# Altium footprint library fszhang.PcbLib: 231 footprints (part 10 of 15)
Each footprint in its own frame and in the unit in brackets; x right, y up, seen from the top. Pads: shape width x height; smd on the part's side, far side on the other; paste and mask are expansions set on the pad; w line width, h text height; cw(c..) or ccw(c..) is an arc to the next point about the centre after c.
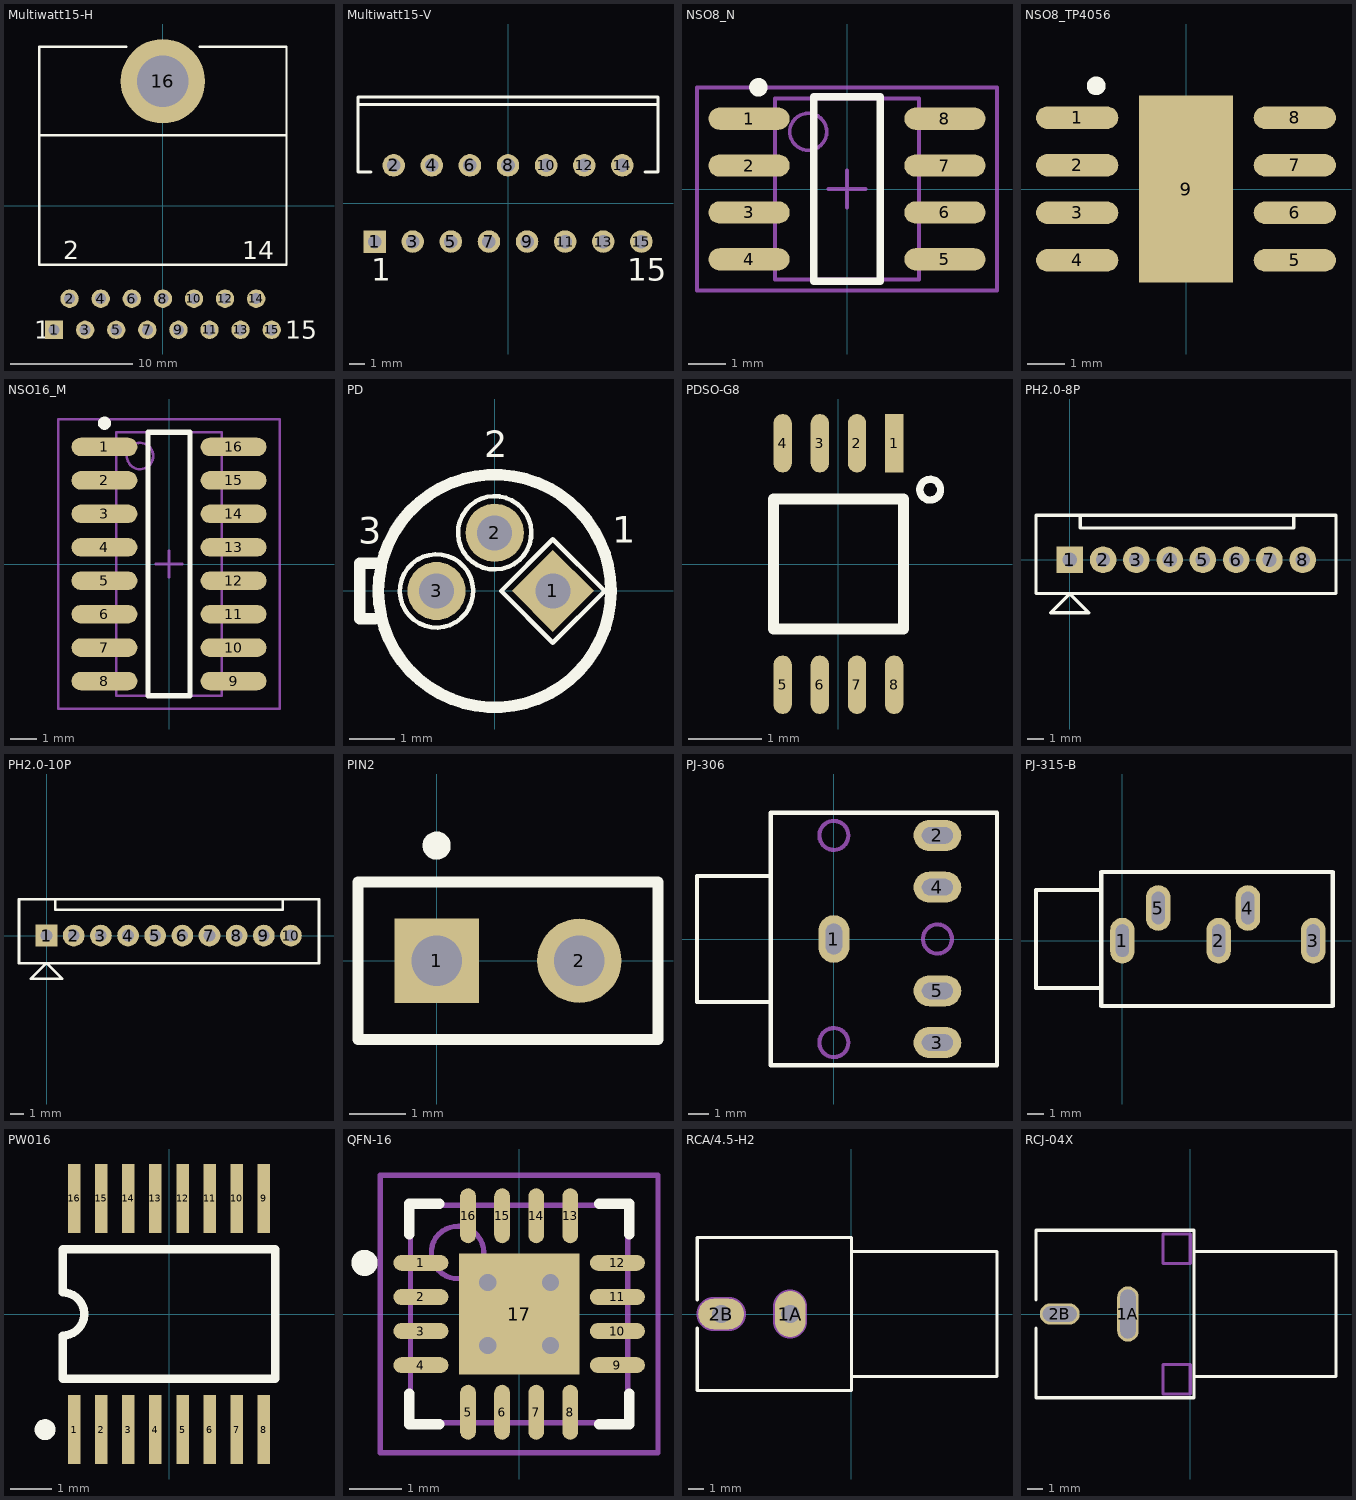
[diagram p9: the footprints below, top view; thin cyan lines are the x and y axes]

## Multiwatt15-H [mm]
height 5
pads (16):
  rect 1.5x1.5 hole 0.9: 1(-8.89,-10.155)
  round 1.5 hole 0.9: 2(-7.62,-7.615) 3(-6.35,-10.155) 4(-5.08,-7.615) 5(-3.81,-10.155) 6(-2.54,-7.615) 7(-1.27,-10.155) 8(0,-7.615) 9(1.27,-10.155) 10(2.54,-7.615) 11(3.81,-10.155) 12(5.08,-7.615) 13(6.35,-10.155) 14(7.62,-7.615) 15(8.89,-10.155)
  round 6.9 hole 4.2: 16(0,10.155)
Top Overlay:
  lines w0.2: -10.1,5.755 10.1,5.755 ; -3,12.955 -10.1,12.955 -10.1,-4.845 10.1,-4.845 10.1,12.955 3,12.955
  text "2" at -8.12,-4.37 h1.5
  text "14" at 6.495,-4.37 h1.5
  text "15" at 10.015,-10.905 h1.5
  text "1" at -10.515,-10.905 h1.5

## Multiwatt15-V [mm]
height 21
pads (15):
  rect 1.5x1.5 hole 0.9: 1(-8.89,-2.54)
  round 1.5 hole 0.9: 2(-7.62,2.54) 3(-6.35,-2.54) 4(-5.08,2.54) 5(-3.81,-2.54) 6(-2.54,2.54) 7(-1.27,-2.54) 8(0,2.54) 9(1.27,-2.54) 10(2.54,2.54) 11(3.81,-2.54) 12(5.08,2.54) 13(6.35,-2.54) 14(7.62,2.54) 15(8.89,-2.54)
Top Overlay:
  lines w0.2: -10,6.59 10,6.59 ; -9.144,2.09 -10,2.09 -10,7.09 10,7.09 10,2.09 9.144,2.09
  text "1" at -9.12,-5.165 h1.5
  text "15" at 7.94,-5.165 h1.5

## NSO8_N [mm] "SOIC-max660"
height 1.75
pads (8):
  oval 2.2x0.6 smd: 1(-2.654,1.905) 2(-2.654,0.635) 3(-2.654,-0.635) 4(-2.654,-1.905) 5(2.654,-1.905) 6(2.654,-0.635) 7(2.654,0.635) 8(2.654,1.905)
Top Overlay:
  circle w0.25: c-2.4,2.755 r0.125
  lines w0.2: -0.9,-2.5 0.9,-2.5 0.9,2.5 -0.9,2.5 -0.9,-2.5
Mechanical 13:
  circle w0.1: c-1.05,1.55 r0.5
  lines w0.1: -1.95,-2.45 1.95,-2.45 1.95,2.45 -1.95,2.45 -1.95,-2.45
Mechanical 15:
  lines w0.1: -0.5,0 0.5,0 ; 0,-0.5 0,0.5 ; -4.064,-2.75 4.064,-2.75 4.064,2.75 -4.064,2.75 -4.064,-2.75
3D body: height 1.75, standoff 0, extent -1.95,-2.45 1.95,2.45

## NSO8_TP4056 [mm] "SOIC-max660"
height 1.75
pads (9):
  oval 2.2x0.6 smd: 1(-2.908,1.905) 2(-2.908,0.635) 3(-2.908,-0.635) 4(-2.908,-1.905) 5(2.908,-1.905) 6(2.908,-0.635) 7(2.908,0.635) 8(2.908,1.905)
  rect 2.5x5 smd: 9(0,0)
Top Overlay:
  circle w0.25: c-2.4,2.755 r0.125

## NSO16_M [mm] "SOIC, 16-Leads, Body 9.9x3.9mm, Pitch 1.27mm, IPC Low Density"
height 1.75
pads (16):
  oval 2.5x0.7 smd: 1(-2.45,4.445) 2(-2.45,3.175) 3(-2.45,1.905) 4(-2.45,0.635) 5(-2.45,-0.635) 6(-2.45,-1.905) 7(-2.45,-3.175) 8(-2.45,-4.445) 9(2.45,-4.445) 10(2.45,-3.175) 11(2.45,-1.905) 12(2.45,-0.635) 13(2.45,0.635) 14(2.45,1.905) 15(2.45,3.175) 16(2.45,4.445)
Top Overlay:
  circle w0.25: c-2.45,5.345 r0.125
  lines w0.2: -0.8,-5 -0.8,5 0.8,5 0.8,-5 -0.8,-5
Mechanical 13:
  circle w0.1: c-1.1,4.1 r0.5
  lines w0.1: -2,-5 -2,5 2,5 2,-5 -2,-5
Mechanical 15:
  lines w0.1: -0.5,0 0.5,0 ; 0,-0.5 0,0.5 ; -4.2,-5.5 -4.2,5.5 4.2,5.5 4.2,-5.5 -4.2,-5.5
3D body: height 1.75, standoff 0, extent -2,-5 2,5

## PD [mil]
pads (3):
  rect 50x50 hole 30 rot 45: 1(50,0)
  round 50 hole 30: 2(0,50) 3(-50,0)
Top Overlay:
  circle w10: c0,0 r100
  lines w3.94: -18.5,1 ccw(c-50,0) -18.5,0.98 ; 5.5,0 50,-44.5 94.5,0 50,44.5 5.5,0 ; 31.5,51 ccw(c0,50) 31.5,50.98
  lines w9.84: -103,-24 -116,-24 -116,24 -102,24
  text "3" at -117.5,33 h39.37
  text "2" at -9,107 h39.37
  text "1" at 101,33.5 h39.37
Bottom Overlay:
  lines w3.94: -18.5,1 ccw(c-50,0) -18.5,0.98 ; 5.5,0 50,44.5 94.5,0 50,-44.5 5.5,0 ; 31.5,51 ccw(c0,50) 31.5,50.98

## PDSO-G8 [mm] "U"
height 4
pads (8):
  rect 0.25x0.8 smd: 1(0.762,1.651)
  oval 0.25x0.8 smd: 2(0.254,1.651) 3(-0.254,1.651) 4(-0.762,1.651) 5(-0.762,-1.651) 6(-0.254,-1.651) 7(0.254,-1.651) 8(0.762,-1.651)
Top Overlay:
  circle w0.1: c1.255,1.016 r0.142
  lines w0.15: -0.889,-0.889 -0.889,0.889 0.889,0.889 0.889,-0.889 -0.889,-0.889

## PH2.0-8P [mm]
height 10
pads (8):
  rect 1.6x1.6 hole 0.86: 1(0,0)
  round 1.6 hole 0.86: 2(2,0) 3(4,0) 4(6,0) 5(8,0) 6(10,0) 7(12,0) 8(14,0)
Top Overlay:
  lines w0.2: 0.635,2.667 0.635,1.905 13.462,1.905 13.462,2.667 ; -2.032,-2.032 16.002,-2.032 16.002,2.667 -2.032,2.667 -2.032,-2.032 ; -1.143,-3.175 1.143,-3.175 0,-2.032 -1.143,-3.175

## PH2.0-10P [mm]
height 10
pads (10):
  rect 1.6x1.6 hole 0.86: 1(0,0)
  round 1.6 hole 0.86: 2(2,0) 3(4,0) 4(6,0) 5(8,0) 6(10,0) 7(12,0) 8(14,0) 9(16,0) 10(18,0)
Top Overlay:
  lines w0.2: 0.635,2.667 0.635,1.905 17.399,1.905 17.399,2.667 ; -2.032,-2.032 -2.032,2.667 20.066,2.667 20.066,-2.032 -2.032,-2.032 ; -1.143,-3.175 0,-2.032 1.143,-3.175 -1.143,-3.175

## PIN2 [mm] "Photosensitive Diode; 2 Leads"
height 2.6
pads (2):
  rect 1.5x1.5 hole 0.9: 1(0,0)
  round 1.5 hole 0.9: 2(2.54,0)
Top Overlay:
  circle w0.25: c0,2.05 r0.125
  lines w0.2: -1.4,-1.4 3.94,-1.4 3.94,1.4 -1.4,1.4 -1.4,-1.4

## PJ-306 [mm] "立体声耳机插座"
pads (5):
  oval 1.5x2.3 hole 0.8 slot 1.5 at 90 deg: 1(0,0)
  oval 2.3x1.5 hole 0.8 slot 1.5 at 0 deg: 2(5,5) 3(5,-5) 4(5,2.5) 5(5,-2.5)
Top Overlay:
  lines w0.2: -3.048,-3.048 -6.604,-3.048 -6.604,3.048 -3.048,3.048 ; -3.048,-6.096 7.874,-6.096 7.874,6.096 -3.048,6.096 -3.048,0 -3.048,-6.096
Mechanical 1:
  circle w0.2: c0,-5 r0.7
  circle w0.2: c0,5 r0.7
  circle w0.2: c5,0 r0.7

## PJ-315-B [mm] "立体声耳机插座"
pads (5):
  oval 1.5x2.8 hole 0.8 slot 2 at 90 deg: 1(0,0) 2(5.9,0) 3(11.7,0) 4(7.7,2) 5(2.2,2)
Top Overlay:
  lines w0.254: -1.3,-2.9 -5.3,-2.9 -5.3,3.1 -1.3,3.1 ; -1.3,-4 12.9,-4 12.9,4.2 -1.3,4.2 -1.3,-4

## PW016 [mm] "Shrink Small Outline; 16 Leads; Body Width 4.4 mm; Pitch 0.65 mm"
height 1.2
pads (16):
  rect 0.3x1.65 smd: 1(-2.275,-2.775) 2(-1.625,-2.775) 3(-0.975,-2.775) 4(-0.325,-2.775) 5(0.325,-2.775) 6(0.975,-2.775) 7(1.625,-2.775) 8(2.275,-2.775) 9(2.275,2.775) 10(1.625,2.775) 11(0.975,2.775) 12(0.325,2.775) 13(-0.325,2.775) 14(-0.975,2.775) 15(-1.625,2.775) 16(-2.275,2.775)
Top Overlay:
  circle w0.25: c-2.975,-2.775 r0.125
  lines w0.2: -2.55,-1.55 -2.55,-0.517 ccw(c-2.55,0) -2.55,0.517 -2.55,1.55 2.55,1.55 2.55,-1.55 -2.55,-1.55

## QFN-16 [mm] "QFN"
height 0.8
pads (17):
  oval 1.05x0.3 smd: 1(-1.875,0.975) 2(-1.875,0.325) 3(-1.875,-0.325) 4(-1.875,-0.975) 9(1.875,-0.975) 10(1.875,-0.325) 11(1.875,0.325) 12(1.875,0.975)
  oval 0.3x1.05 smd: 5(-0.975,-1.875) 6(-0.325,-1.875) 7(0.325,-1.875) 8(0.975,-1.875) 13(0.975,1.875) 14(0.325,1.875) 15(-0.325,1.875) 16(-0.975,1.875)
  rect 2.3x2.3 smd: 17(0,0)
via -0.6,0.6 diameter 0.66 hole 0.33
via 0.6,0.6 diameter 0.66 hole 0.33
via -0.6,-0.6 diameter 0.66 hole 0.33
via 0.6,-0.6 diameter 0.66 hole 0.33
Top Overlay:
  circle w0.25: c-2.95,0.975 r0.125
  lines w0.2: -2.1,-1.525 -2.1,-2.1 -1.525,-2.1 ; -2.1,1.525 -2.1,2.1 -1.525,2.1 ; 1.525,-2.1 2.1,-2.1 2.1,-1.525 ; 1.525,2.1 2.1,2.1 2.1,1.525
Mechanical 13:
  circle w0.1: c-1.175,1.175 r0.5
  lines w0.1: -2.075,-2.075 -2.075,2.075 2.075,2.075 2.075,-2.075 -2.075,-2.075
Mechanical 15:
  lines w0.1: -0.5,0 0.5,0 ; 0,-0.5 0,0.5 ; -2.65,-2.65 -2.65,2.65 2.65,2.65 2.65,-2.65 -2.65,-2.65
3D body: height 0.8, standoff 0, extent -2.075,-2.075 2.075,2.075

## RCA/4.5-H2 [mm] "Two Conductor Jack (RCA)"
height 13
pads (2):
  oval 2x3 hole 1.2: 1A(-4,0)
  oval 3x2 hole 1.2: 2B(-8.496,0)
Top Overlay:
  lines w0.2: -10.075,5 -0.018,5 ; -10.057,-0.92 -10.057,-5 0,-5 0,5 ; -10.057,0.92 -10.057,5 ; 0,-4.065 9.5,-4.065 9.5,4.065 0,4.065
Mechanical 1:
  lines w1.2: -8.996,0 -7.996,0 ; -4,-0.5 -4,0.5
Mechanical 2:
  lines w2.216: -8.996,0 -7.996,0 ; -4,-0.5 -4,0.5

## RCJ-04X [mm] "Two Conductor Jack (RCA)"
height 13
pads (2):
  oval 1.4x3.6 hole 1 slot 3.2 at 90 deg: 1A(-4.064,0)
  oval 2.6x1.4 hole 1 slot 2.2 at 0 deg: 2B(-8.509,0)
Top Overlay:
  lines w0.2: -10.057,-0.92 -10.057,-5.461 0.254,-5.461 0.254,5.461 -10.057,5.461 -10.057,0.92 ; 0.254,-4.065 9.5,-4.065 9.5,4.065 0.254,4.065
Mechanical 1:
  lines w0.2: -1.778,-5.207 0,-5.207 0,-3.302 -1.778,-3.302 -1.778,-5.207 ; -1.778,3.302 -1.778,5.207 0,5.207 0,3.302 -1.778,3.302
